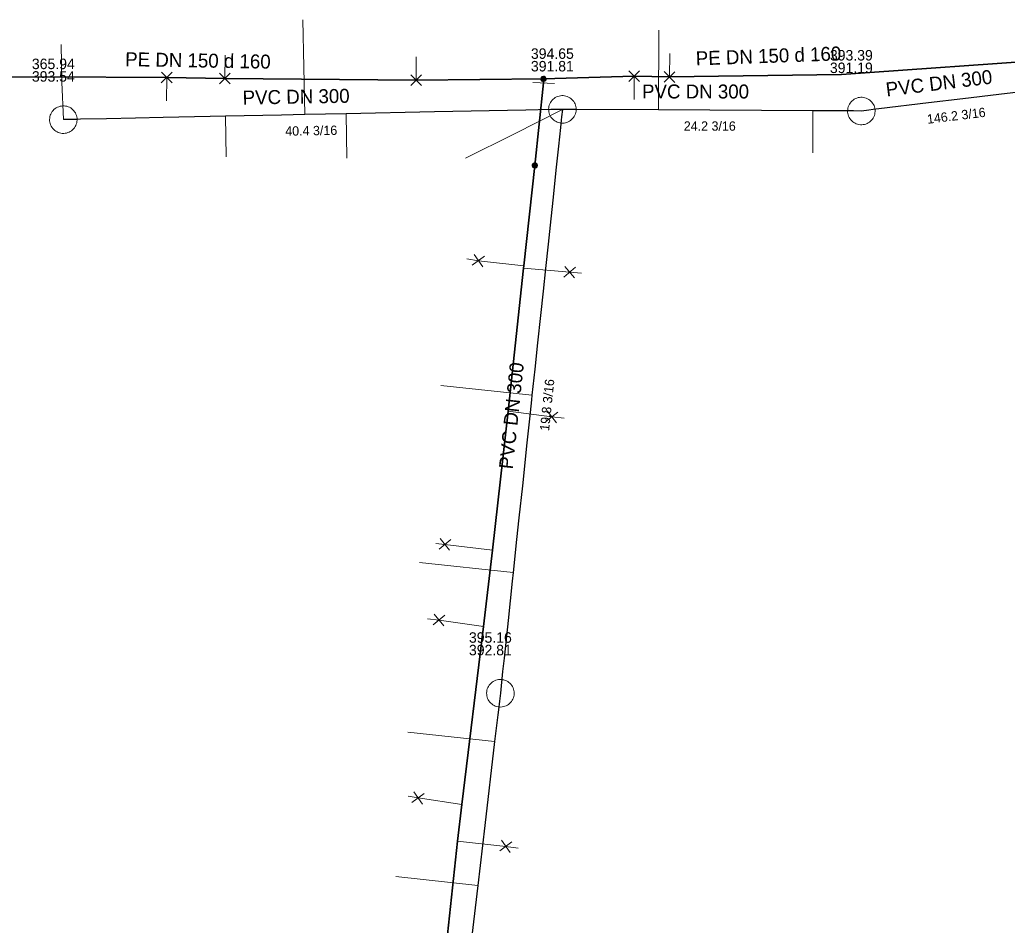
# Model space of a CAD drawing. Extents: x -772952 to -772403, y -1033777 to -1033210.
# Drawn here: x -772723 to -772638.2, y -1033418.1 to -1033340.4 of the extents above; entities that cross this region are included whole.
import ezdxf

# ---------------------------------------------------------------- set-up
doc = ezdxf.new("R2010")
doc.units = 0
doc.header["$LTSCALE"] = 0.36
for name, color, linetype, lineweight in [('15', 7, 'Continuous', 13), ('16', 7, 'Continuous', 35), ('2', 7, 'Continuous', 25), ('4', 7, 'Continuous', 13), ('57', 7, 'Continuous', 13), ('59', 7, 'Continuous', 13)]:
    doc.layers.add(name, color=color, linetype=linetype, lineweight=lineweight)
for name, color, linetype in [('17', 7, 'Continuous'), ('3', 7, 'Continuous'), ('6', 7, 'Continuous')]:
    doc.layers.add(name, color=color, linetype=linetype)

msp = doc.modelspace()

# ---------------------------------------------------------------- linework, layer by layer
at = {"layer": '15'}
for p, q in [((-772709.888, -1033344.951), (-772710.814, -1033345.849)), ((-772710.803, -1033344.935), (-772709.894, -1033345.866)), ((-772705.822, -1033345.938), (-772704.894, -1033345.04)), ((-772704.907, -1033345.955), (-772705.814, -1033345.022)), ((-772688.48, -1033346.089), (-772689.401, -1033345.168)), ((-772689.395, -1033346.084), (-772688.481, -1033345.174)), ((-772670.69, -1033344.821), (-772669.767, -1033345.74)), ((-772669.775, -1033344.824), (-772670.687, -1033345.736)), ((-772666.733, -1033345.822), (-772667.648, -1033344.895)), ((-772667.648, -1033345.811), (-772666.728, -1033344.907)), ((-772678.929, -1033345.833), (-772677.069, -1033345.906)), ((-772683.218, -1033361.646), (-772683.974, -1033360.6)), ((-772683.07, -1033360.743), (-772684.123, -1033361.508)), ((-772676.26, -1033362.528), (-772675.264, -1033361.689)), ((-772676.178, -1033361.616), (-772675.349, -1033362.606)), ((-772677.807, -1033374.91), (-772676.778, -1033374.113)), ((-772677.687, -1033374.003), (-772676.9, -1033375.025)), ((-772685.968, -1033385.054), (-772686.977, -1033385.877)), ((-772686.065, -1033385.964), (-772686.879, -1033384.962)), ((-772686.47, -1033391.552), (-772687.475, -1033392.379)), ((-772686.563, -1033392.462), (-772687.381, -1033391.464)), ((-772688.25, -1033406.848), (-772689.31, -1033407.604)), ((-772688.405, -1033407.75), (-772689.152, -1033406.698)), ((-772681.769, -1033411.762), (-772680.718, -1033410.995)), ((-772681.624, -1033410.859), (-772680.865, -1033411.903))]:
    msp.add_line(p, q, dxfattribs=at)
for points in [[(-772677.779, -1033345.53), (-772677.785, -1033345.478), (-772677.802, -1033345.428), (-772677.831, -1033345.384), (-772677.868, -1033345.347), (-772677.913, -1033345.32), (-772677.963, -1033345.303), (-772678.016, -1033345.299), (-772678.068, -1033345.306), (-772678.117, -1033345.325), (-772678.16, -1033345.354), (-772678.196, -1033345.393), (-772678.222, -1033345.438), (-772678.238, -1033345.489), (-772678.241, -1033345.541), (-772678.233, -1033345.593), (-772678.213, -1033345.642), (-772678.182, -1033345.685), (-772678.143, -1033345.719), (-772678.097, -1033345.745), (-772678.046, -1033345.759), (-772677.993, -1033345.761), (-772677.942, -1033345.751), (-772677.894, -1033345.73), (-772677.851, -1033345.699), (-772677.817, -1033345.658), (-772677.793, -1033345.612), (-772677.781, -1033345.561)], [(-772677.809, -1033345.53), (-772677.815, -1033345.481), (-772677.832, -1033345.435), (-772677.86, -1033345.395), (-772677.897, -1033345.363), (-772677.941, -1033345.341), (-772677.989, -1033345.33), (-772678.038, -1033345.33), (-772678.085, -1033345.343), (-772678.128, -1033345.367), (-772678.164, -1033345.4), (-772678.191, -1033345.441), (-772678.207, -1033345.488), (-772678.211, -1033345.537), (-772678.204, -1033345.585), (-772678.185, -1033345.63), (-772678.155, -1033345.67), (-772678.117, -1033345.701), (-772678.073, -1033345.721), (-772678.025, -1033345.731), (-772677.976, -1033345.729), (-772677.929, -1033345.714), (-772677.886, -1033345.689), (-772677.852, -1033345.655), (-772677.826, -1033345.613), (-772677.812, -1033345.566)], [(-772677.839, -1033345.53), (-772677.845, -1033345.485), (-772677.862, -1033345.443), (-772677.89, -1033345.408), (-772677.926, -1033345.381), (-772677.968, -1033345.364), (-772678.013, -1033345.359), (-772678.058, -1033345.365), (-772678.099, -1033345.384), (-772678.134, -1033345.412), (-772678.161, -1033345.449), (-772678.177, -1033345.491), (-772678.181, -1033345.536), (-772678.174, -1033345.581), (-772678.155, -1033345.622), (-772678.126, -1033345.656), (-772678.089, -1033345.682), (-772678.046, -1033345.698), (-772678.001, -1033345.701), (-772677.956, -1033345.693), (-772677.916, -1033345.673), (-772677.882, -1033345.644), (-772677.856, -1033345.606), (-772677.842, -1033345.563)], [(-772677.869, -1033345.53), (-772677.874, -1033345.489), (-772677.892, -1033345.452), (-772677.919, -1033345.421), (-772677.954, -1033345.4), (-772677.994, -1033345.389), (-772678.035, -1033345.391), (-772678.074, -1033345.404), (-772678.108, -1033345.428), (-772678.133, -1033345.46), (-772678.148, -1033345.498), (-772678.151, -1033345.539), (-772678.143, -1033345.579), (-772678.123, -1033345.615), (-772678.094, -1033345.644), (-772678.057, -1033345.663), (-772678.017, -1033345.671), (-772677.976, -1033345.667), (-772677.938, -1033345.652), (-772677.906, -1033345.626), (-772677.883, -1033345.592), (-772677.87, -1033345.553)], [(-772677.899, -1033345.53), (-772677.904, -1033345.494), (-772677.922, -1033345.462), (-772677.948, -1033345.437), (-772677.982, -1033345.422), (-772678.018, -1033345.419), (-772678.053, -1033345.427), (-772678.084, -1033345.447), (-772678.107, -1033345.475), (-772678.12, -1033345.509), (-772678.12, -1033345.546), (-772678.109, -1033345.581), (-772678.088, -1033345.61), (-772678.058, -1033345.631), (-772678.023, -1033345.641), (-772677.986, -1033345.639), (-772677.952, -1033345.625), (-772677.925, -1033345.602), (-772677.906, -1033345.57), (-772677.899, -1033345.535)], [(-772677.929, -1033345.53), (-772677.934, -1033345.499), (-772677.951, -1033345.473), (-772677.977, -1033345.456), (-772678.007, -1033345.449), (-772678.038, -1033345.453), (-772678.065, -1033345.47), (-772678.083, -1033345.494), (-772678.091, -1033345.525), (-772678.087, -1033345.555), (-772678.072, -1033345.583), (-772678.048, -1033345.602), (-772678.018, -1033345.611), (-772677.987, -1033345.608), (-772677.959, -1033345.594), (-772677.939, -1033345.57), (-772677.929, -1033345.541)], [(-772677.959, -1033345.53), (-772677.964, -1033345.506), (-772677.981, -1033345.488), (-772678.004, -1033345.479), (-772678.028, -1033345.482), (-772678.049, -1033345.496), (-772678.06, -1033345.518), (-772678.06, -1033345.543), (-772678.048, -1033345.564), (-772678.028, -1033345.578), (-772678.003, -1033345.581), (-772677.98, -1033345.572), (-772677.964, -1033345.554)], [(-772677.989, -1033345.53), (-772677.994, -1033345.515), (-772678.009, -1033345.509), (-772678.024, -1033345.513), (-772678.031, -1033345.527), (-772678.027, -1033345.542), (-772678.014, -1033345.551), (-772677.999, -1033345.548), (-772677.989, -1033345.536)], [(-772678.529, -1033352.95), (-772678.535, -1033352.898), (-772678.552, -1033352.848), (-772678.581, -1033352.804), (-772678.618, -1033352.767), (-772678.663, -1033352.74), (-772678.713, -1033352.723), (-772678.766, -1033352.719), (-772678.818, -1033352.726), (-772678.867, -1033352.745), (-772678.91, -1033352.774), (-772678.946, -1033352.813), (-772678.972, -1033352.858), (-772678.988, -1033352.909), (-772678.991, -1033352.961), (-772678.983, -1033353.013), (-772678.963, -1033353.062), (-772678.932, -1033353.105), (-772678.893, -1033353.139), (-772678.847, -1033353.165), (-772678.796, -1033353.179), (-772678.743, -1033353.181), (-772678.692, -1033353.171), (-772678.644, -1033353.15), (-772678.601, -1033353.119), (-772678.567, -1033353.078), (-772678.543, -1033353.032), (-772678.531, -1033352.981)], [(-772678.559, -1033352.95), (-772678.565, -1033352.901), (-772678.582, -1033352.855), (-772678.61, -1033352.815), (-772678.647, -1033352.783), (-772678.691, -1033352.761), (-772678.739, -1033352.75), (-772678.788, -1033352.75), (-772678.835, -1033352.763), (-772678.878, -1033352.787), (-772678.914, -1033352.82), (-772678.941, -1033352.861), (-772678.957, -1033352.908), (-772678.961, -1033352.957), (-772678.954, -1033353.005), (-772678.935, -1033353.05), (-772678.905, -1033353.09), (-772678.867, -1033353.121), (-772678.823, -1033353.141), (-772678.775, -1033353.151), (-772678.726, -1033353.149), (-772678.679, -1033353.134), (-772678.636, -1033353.109), (-772678.602, -1033353.075), (-772678.576, -1033353.033), (-772678.562, -1033352.986)], [(-772678.589, -1033352.95), (-772678.595, -1033352.905), (-772678.612, -1033352.863), (-772678.64, -1033352.828), (-772678.676, -1033352.801), (-772678.718, -1033352.784), (-772678.763, -1033352.779), (-772678.808, -1033352.785), (-772678.849, -1033352.804), (-772678.884, -1033352.832), (-772678.911, -1033352.869), (-772678.927, -1033352.911), (-772678.931, -1033352.956), (-772678.924, -1033353.001), (-772678.905, -1033353.042), (-772678.876, -1033353.076), (-772678.839, -1033353.102), (-772678.796, -1033353.118), (-772678.751, -1033353.121), (-772678.706, -1033353.113), (-772678.666, -1033353.093), (-772678.632, -1033353.064), (-772678.606, -1033353.026), (-772678.592, -1033352.983)], [(-772678.619, -1033352.95), (-772678.624, -1033352.909), (-772678.642, -1033352.872), (-772678.669, -1033352.841), (-772678.704, -1033352.82), (-772678.744, -1033352.809), (-772678.785, -1033352.811), (-772678.824, -1033352.824), (-772678.858, -1033352.848), (-772678.883, -1033352.88), (-772678.898, -1033352.918), (-772678.901, -1033352.959), (-772678.893, -1033352.999), (-772678.873, -1033353.035), (-772678.844, -1033353.064), (-772678.807, -1033353.083), (-772678.767, -1033353.091), (-772678.726, -1033353.087), (-772678.688, -1033353.072), (-772678.656, -1033353.046), (-772678.633, -1033353.012), (-772678.62, -1033352.973)], [(-772678.649, -1033352.95), (-772678.654, -1033352.914), (-772678.672, -1033352.882), (-772678.698, -1033352.857), (-772678.732, -1033352.842), (-772678.768, -1033352.839), (-772678.803, -1033352.847), (-772678.834, -1033352.867), (-772678.857, -1033352.895), (-772678.87, -1033352.929), (-772678.87, -1033352.966), (-772678.859, -1033353.001), (-772678.838, -1033353.03), (-772678.808, -1033353.051), (-772678.773, -1033353.061), (-772678.736, -1033353.059), (-772678.702, -1033353.045), (-772678.675, -1033353.022), (-772678.656, -1033352.99), (-772678.649, -1033352.955)], [(-772678.679, -1033352.95), (-772678.684, -1033352.919), (-772678.701, -1033352.893), (-772678.727, -1033352.876), (-772678.757, -1033352.869), (-772678.788, -1033352.873), (-772678.815, -1033352.89), (-772678.833, -1033352.914), (-772678.841, -1033352.945), (-772678.837, -1033352.975), (-772678.822, -1033353.003), (-772678.798, -1033353.022), (-772678.768, -1033353.031), (-772678.737, -1033353.028), (-772678.709, -1033353.014), (-772678.689, -1033352.99), (-772678.679, -1033352.961)], [(-772678.709, -1033352.95), (-772678.714, -1033352.926), (-772678.731, -1033352.908), (-772678.754, -1033352.899), (-772678.778, -1033352.902), (-772678.799, -1033352.916), (-772678.81, -1033352.938), (-772678.81, -1033352.963), (-772678.798, -1033352.984), (-772678.778, -1033352.998), (-772678.753, -1033353.001), (-772678.73, -1033352.992), (-772678.714, -1033352.974)], [(-772678.739, -1033352.95), (-772678.744, -1033352.935), (-772678.759, -1033352.929), (-772678.774, -1033352.933), (-772678.781, -1033352.947), (-772678.777, -1033352.962), (-772678.764, -1033352.971), (-772678.749, -1033352.968), (-772678.739, -1033352.956)]]:
    msp.add_lwpolyline(points, close=True, dxfattribs=at)
at = {"layer": '16'}
for p, q in [((-772678.76, -1033352.95), (-772678, -1033345.87)), ((-772678, -1033345.87), (-772678.01, -1033345.53))]:
    msp.add_line(p, q, dxfattribs=at)
for points in [[(-772678.01, -1033345.53), (-772670.23, -1033345.28), (-772667.19, -1033345.359), (-772652.429, -1033345.14), (-772633.819, -1033343.84)], [(-772731.85, -1033345.57), (-772728.609, -1033345.41), (-772720.769, -1033345.339), (-772710.35, -1033345.399), (-772705.359, -1033345.489), (-772688.94, -1033345.629), (-772678.01, -1033345.53)], [(-772696.925, -1033516.445), (-772694.923, -1033498.129), (-772694.383, -1033493.587), (-772693.835, -1033487.579), (-772692.73, -1033477.131), (-772692.473, -1033475.508), (-772691.35, -1033464.888), (-772691.161, -1033463.185), (-772688.866, -1033442.589), (-772687.791, -1033432.589), (-772687.787, -1033432.396), (-772686.579, -1033422.136), (-772685.397, -1033410.938), (-772685.032, -1033407.78), (-772683.147, -1033392.504), (-772682.401, -1033385.967), (-772681.054, -1033374.035), (-772679.728, -1033361.771), (-772679.71, -1033361.563), (-772678.76, -1033352.949)]]:
    msp.add_lwpolyline(points, dxfattribs=at)
at = {"layer": '2'}
for points in [[(-772634.23, -1033346.29), (-772635.232, -1033346.41), (-772636.035, -1033346.507), (-772638.931, -1033346.857), (-772642.03, -1033347.23), (-772644.969, -1033347.585), (-772649.229, -1033348.099), (-772649.71, -1033348.157), (-772650.097, -1033348.203), (-772650.73, -1033348.28)], [(-772676.39, -1033348.14), (-772677.081, -1033348.154), (-772677.381, -1033348.16), (-772679.516, -1033348.204), (-772687.354, -1033348.365), (-772694.957, -1033348.521), (-772698.501, -1033348.586), (-772700.488, -1033348.635), (-772705.293, -1033348.733), (-772706.628, -1033348.761), (-772710.666, -1033348.844), (-772713.037, -1033348.892), (-772715.524, -1033348.944), (-772717.758, -1033348.989), (-772718.083, -1033348.996), (-772718.521, -1033349.005), (-772719.22, -1033349.02)], [(-772676.39, -1033348.14), (-772676.457, -1033348.774), (-772676.487, -1033349.054), (-772676.555, -1033349.697), (-772676.724, -1033351.284), (-772676.945, -1033353.365), (-772677.191, -1033355.679), (-772677.389, -1033357.54), (-772677.62, -1033359.717), (-772677.842, -1033361.8), (-772678.047, -1033363.729), (-772678.271, -1033365.838), (-772678.519, -1033368.166), (-772678.759, -1033370.43), (-772678.998, -1033372.678), (-772679.038, -1033373.054), (-772679.212, -1033374.69), (-772679.431, -1033376.747), (-772679.825, -1033380.454), (-772680.117, -1033383.202), (-772680.315, -1033385.063), (-772680.615, -1033387.881), (-772680.695, -1033388.634), (-772681.052, -1033391.999), (-772681.397, -1033395.24), (-772681.516, -1033396.363), (-772681.71, -1033398.243)], [(-772650.73, -1033348.28), (-772651.399, -1033348.276), (-772652.137, -1033348.272), (-772654.897, -1033348.257), (-772668.149, -1033348.184), (-772675.198, -1033348.146), (-772675.76, -1033348.143), (-772676.122, -1033348.141), (-772676.39, -1033348.14)], [(-772681.71, -1033398.243), (-772681.796, -1033398.917), (-772681.884, -1033399.66), (-772681.935, -1033400.093), (-772682.205, -1033402.39), (-772683.053, -1033409.588), (-772683.658, -1033414.727), (-772684.676, -1033423.371), (-772684.962, -1033425.8), (-772685.341, -1033429.02), (-772685.405, -1033429.57), (-772685.664, -1033431.77), (-772686.265, -1033436.869), (-772686.892, -1033442.194), (-772686.984, -1033442.98), (-772687.333, -1033445.942), (-772687.413, -1033446.622), (-772687.57, -1033447.95)]]:
    msp.add_lwpolyline(points, dxfattribs=at)
at = {"layer": '4'}
for points in [[(-772675.21, -1033348.14), (-772675.216, -1033348.021), (-772675.234, -1033347.904), (-772675.263, -1033347.788), (-772675.304, -1033347.677), (-772675.356, -1033347.57), (-772675.419, -1033347.469), (-772675.492, -1033347.374), (-772675.573, -1033347.288), (-772675.663, -1033347.21), (-772675.761, -1033347.141), (-772675.864, -1033347.083), (-772675.973, -1033347.036), (-772676.087, -1033346.999), (-772676.203, -1033346.974), (-772676.321, -1033346.962), (-772676.44, -1033346.961), (-772676.559, -1033346.972), (-772676.675, -1033346.995), (-772676.789, -1033347.029), (-772676.899, -1033347.075), (-772677.004, -1033347.132), (-772677.102, -1033347.199), (-772677.193, -1033347.275), (-772677.276, -1033347.36), (-772677.35, -1033347.454), (-772677.414, -1033347.554), (-772677.468, -1033347.66), (-772677.511, -1033347.771), (-772677.543, -1033347.885), (-772677.562, -1033348.003), (-772677.57, -1033348.122), (-772677.566, -1033348.24), (-772677.55, -1033348.358), (-772677.522, -1033348.474), (-772677.483, -1033348.586), (-772677.432, -1033348.694), (-772677.371, -1033348.796), (-772677.3, -1033348.892), (-772677.22, -1033348.979), (-772677.131, -1033349.059), (-772677.035, -1033349.129), (-772676.932, -1033349.189), (-772676.824, -1033349.238), (-772676.711, -1033349.276), (-772676.595, -1033349.302), (-772676.477, -1033349.317), (-772676.358, -1033349.32), (-772676.24, -1033349.311), (-772676.122, -1033349.29), (-772676.008, -1033349.257), (-772675.898, -1033349.213), (-772675.792, -1033349.158), (-772675.693, -1033349.092), (-772675.6, -1033349.017), (-772675.516, -1033348.933), (-772675.441, -1033348.841), (-772675.375, -1033348.742), (-772675.319, -1033348.637), (-772675.275, -1033348.527), (-772675.241, -1033348.413), (-772675.22, -1033348.296), (-772675.21, -1033348.177)], [(-772649.549, -1033348.28), (-772649.556, -1033348.161), (-772649.574, -1033348.044), (-772649.603, -1033347.928), (-772649.644, -1033347.817), (-772649.696, -1033347.71), (-772649.759, -1033347.609), (-772649.831, -1033347.514), (-772649.913, -1033347.428), (-772650.003, -1033347.35), (-772650.101, -1033347.281), (-772650.204, -1033347.223), (-772650.313, -1033347.176), (-772650.427, -1033347.139), (-772650.543, -1033347.114), (-772650.661, -1033347.102), (-772650.78, -1033347.101), (-772650.899, -1033347.112), (-772651.015, -1033347.135), (-772651.129, -1033347.169), (-772651.239, -1033347.215), (-772651.343, -1033347.272), (-772651.442, -1033347.339), (-772651.532, -1033347.415), (-772651.616, -1033347.5), (-772651.69, -1033347.594), (-772651.754, -1033347.694), (-772651.808, -1033347.8), (-772651.851, -1033347.911), (-772651.883, -1033348.025), (-772651.902, -1033348.143), (-772651.91, -1033348.262), (-772651.906, -1033348.38), (-772651.89, -1033348.498), (-772651.862, -1033348.614), (-772651.823, -1033348.726), (-772651.772, -1033348.834), (-772651.711, -1033348.936), (-772651.64, -1033349.032), (-772651.559, -1033349.119), (-772651.471, -1033349.199), (-772651.375, -1033349.269), (-772651.272, -1033349.329), (-772651.164, -1033349.378), (-772651.051, -1033349.416), (-772650.934, -1033349.442), (-772650.817, -1033349.457), (-772650.698, -1033349.46), (-772650.58, -1033349.451), (-772650.462, -1033349.43), (-772650.348, -1033349.397), (-772650.238, -1033349.353), (-772650.132, -1033349.298), (-772650.032, -1033349.232), (-772649.94, -1033349.157), (-772649.856, -1033349.073), (-772649.781, -1033348.981), (-772649.715, -1033348.882), (-772649.659, -1033348.777), (-772649.615, -1033348.667), (-772649.581, -1033348.553), (-772649.559, -1033348.436), (-772649.549, -1033348.317)], [(-772718.039, -1033349.02), (-772718.046, -1033348.901), (-772718.064, -1033348.784), (-772718.093, -1033348.668), (-772718.134, -1033348.557), (-772718.186, -1033348.45), (-772718.249, -1033348.349), (-772718.321, -1033348.254), (-772718.402, -1033348.168), (-772718.493, -1033348.09), (-772718.591, -1033348.021), (-772718.694, -1033347.963), (-772718.803, -1033347.916), (-772718.917, -1033347.879), (-772719.032, -1033347.854), (-772719.151, -1033347.842), (-772719.27, -1033347.841), (-772719.389, -1033347.852), (-772719.505, -1033347.875), (-772719.619, -1033347.909), (-772719.728, -1033347.955), (-772719.833, -1033348.012), (-772719.932, -1033348.079), (-772720.022, -1033348.155), (-772720.106, -1033348.24), (-772720.179, -1033348.334), (-772720.244, -1033348.434), (-772720.298, -1033348.54), (-772720.341, -1033348.651), (-772720.373, -1033348.765), (-772720.392, -1033348.883), (-772720.4, -1033349.002), (-772720.396, -1033349.12), (-772720.38, -1033349.238), (-772720.352, -1033349.354), (-772720.313, -1033349.466), (-772720.262, -1033349.574), (-772720.201, -1033349.676), (-772720.13, -1033349.772), (-772720.049, -1033349.859), (-772719.961, -1033349.939), (-772719.865, -1033350.009), (-772719.762, -1033350.069), (-772719.654, -1033350.118), (-772719.541, -1033350.156), (-772719.424, -1033350.182), (-772719.307, -1033350.197), (-772719.188, -1033350.2), (-772719.07, -1033350.191), (-772718.951, -1033350.17), (-772718.838, -1033350.137), (-772718.728, -1033350.093), (-772718.622, -1033350.038), (-772718.522, -1033349.972), (-772718.429, -1033349.897), (-772718.346, -1033349.813), (-772718.271, -1033349.721), (-772718.205, -1033349.622), (-772718.149, -1033349.517), (-772718.105, -1033349.407), (-772718.071, -1033349.293), (-772718.049, -1033349.176), (-772718.039, -1033349.057)], [(-772680.529, -1033398.243), (-772680.536, -1033398.124), (-772680.554, -1033398.007), (-772680.583, -1033397.891), (-772680.624, -1033397.78), (-772680.676, -1033397.673), (-772680.739, -1033397.572), (-772680.811, -1033397.477), (-772680.892, -1033397.391), (-772680.983, -1033397.313), (-772681.081, -1033397.244), (-772681.184, -1033397.186), (-772681.293, -1033397.139), (-772681.407, -1033397.102), (-772681.522, -1033397.077), (-772681.641, -1033397.065), (-772681.76, -1033397.064), (-772681.879, -1033397.075), (-772681.995, -1033397.098), (-772682.108, -1033397.132), (-772682.218, -1033397.178), (-772682.323, -1033397.235), (-772682.422, -1033397.302), (-772682.512, -1033397.378), (-772682.596, -1033397.463), (-772682.669, -1033397.557), (-772682.733, -1033397.657), (-772682.788, -1033397.763), (-772682.831, -1033397.874), (-772682.863, -1033397.988), (-772682.882, -1033398.106), (-772682.89, -1033398.225), (-772682.886, -1033398.343), (-772682.87, -1033398.461), (-772682.842, -1033398.577), (-772682.803, -1033398.689), (-772682.752, -1033398.797), (-772682.691, -1033398.899), (-772682.62, -1033398.995), (-772682.539, -1033399.082), (-772682.451, -1033399.162), (-772682.355, -1033399.232), (-772682.252, -1033399.292), (-772682.144, -1033399.341), (-772682.031, -1033399.379), (-772681.914, -1033399.405), (-772681.797, -1033399.42), (-772681.678, -1033399.423), (-772681.559, -1033399.414), (-772681.441, -1033399.393), (-772681.328, -1033399.36), (-772681.218, -1033399.316), (-772681.112, -1033399.261), (-772681.012, -1033399.195), (-772680.919, -1033399.12), (-772680.836, -1033399.036), (-772680.761, -1033398.944), (-772680.695, -1033398.845), (-772680.639, -1033398.74), (-772680.595, -1033398.63), (-772680.561, -1033398.516), (-772680.539, -1033398.399), (-772680.529, -1033398.28)]]:
    msp.add_lwpolyline(points, close=True, dxfattribs=at)
at = {"layer": '57'}
for p, q in [((-772698.501, -1033348.586), (-772698.67, -1033340.45)), ((-772668.149, -1033348.184), (-772668.11, -1033341.34)), ((-772705.293, -1033348.733), (-772705.24, -1033352.22)), ((-772694.957, -1033348.521), (-772694.88, -1033352.32)), ((-772654.897, -1033348.257), (-772654.9, -1033351.87)), ((-772678.998, -1033372.678), (-772686.82, -1033371.84)), ((-772680.615, -1033387.881), (-772688.65, -1033387.01)), ((-772682.205, -1033402.39), (-772689.66, -1033401.58)), ((-772683.658, -1033414.727), (-772690.67, -1033413.96))]:
    msp.add_line(p, q, dxfattribs=at)
for points in [[(-772719.22, -1033349.02), (-772719.345, -1033345.815), (-772719.41, -1033342.56)], [(-772676.39, -1033348.14), (-772680.57, -1033350.255), (-772684.7, -1033352.32)]]:
    msp.add_lwpolyline(points, dxfattribs=at)
at = {"layer": '59'}
for p, q in [((-772705.359, -1033345.489), (-772705.333, -1033343.489)), ((-772688.94, -1033345.629), (-772688.94, -1033343.629)), ((-772667.19, -1033345.359), (-772667.179, -1033343.359)), ((-772710.35, -1033345.399), (-772710.374, -1033347.399)), ((-772670.23, -1033345.28), (-772670.223, -1033347.28))]:
    msp.add_line(p, q, dxfattribs=at)
for points in [[(-772679.71, -1033361.564), (-772683.596, -1033361.125), (-772684.58, -1033360.969)], [(-772679.728, -1033361.772), (-772675.764, -1033362.11), (-772674.755, -1033362.197)], [(-772681.055, -1033374.036), (-772677.294, -1033374.513), (-772676.232, -1033374.649)], [(-772682.401, -1033385.967), (-772686.471, -1033385.464), (-772687.258, -1033385.386)], [(-772683.148, -1033392.504), (-772686.972, -1033391.965), (-772687.966, -1033391.869)], [(-772685.033, -1033407.781), (-772688.779, -1033407.226), (-772689.612, -1033407.087)], [(-772685.398, -1033410.938), (-772681.245, -1033411.38), (-772680.171, -1033411.547)]]:
    msp.add_lwpolyline(points, dxfattribs=at)

# ---------------------------------------------------------------- texts
at = {"layer": '17'}
for rotation, p in [(2, (-772664.921, -1033344.369)), (359, (-772713.921, -1033344.431))]:
    msp.add_text('PE DN 150 d 160 ', height=1.2, rotation=rotation, dxfattribs=at).set_placement(p)
at = {"layer": '3'}
for s, height, rotation, p in [('PVC DN 300', 1.2, 7, (-772648.553, -1033347.038)), ('PVC DN 300', 1.2, 1, (-772703.824, -1033347.731)), ('146.2 3/16 ', 0.8, 7, (-772645.045, -1033349.382)), ('40.4 3/16', 0.8, 1, (-772700.168, -1033350.405)), ('PVC DN 300', 1.2, 84, (-772680.648, -1033379.055)), ('19.8 3/16', 0.8, 84, (-772677.536, -1033375.763))]:
    msp.add_text(s, height=height, rotation=rotation, dxfattribs=at).set_placement(p)
for s, height, p in [('PVC DN 300', 1.2, (-772669.555, -1033347.206)), ('24.2 3/16', 0.8, (-772665.969, -1033349.972))]:
    msp.add_text(s, height=height, dxfattribs=at).set_placement(p)
at = {"layer": '6'}
for s, p in [('394.65', (-772679.088, -1033343.807)), ('365.94', (-772721.918, -1033344.687)), ('393.39', (-772653.428, -1033343.947)), ('391.81', (-772679.088, -1033344.884)), ('391.19', (-772653.428, -1033345.024)), ('393.54', (-772721.918, -1033345.764)), ('395.16', (-772684.408, -1033393.91)), ('392.81', (-772684.408, -1033394.987))]:
    msp.add_text(s, height=0.9, dxfattribs=at).set_placement(p)

doc.saveas('drawing.dxf')
